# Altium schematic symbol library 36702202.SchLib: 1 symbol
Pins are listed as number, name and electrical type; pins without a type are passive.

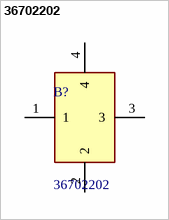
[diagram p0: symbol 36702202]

## 36702202
designator B?
WE-SHC Two-piece Seamless Shielding Cabinet; Manufacturer_Name: Wurth Elektronik; Geometry.Height: 3mm
footprint 36702202
pins: 1, 2, 3, 4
